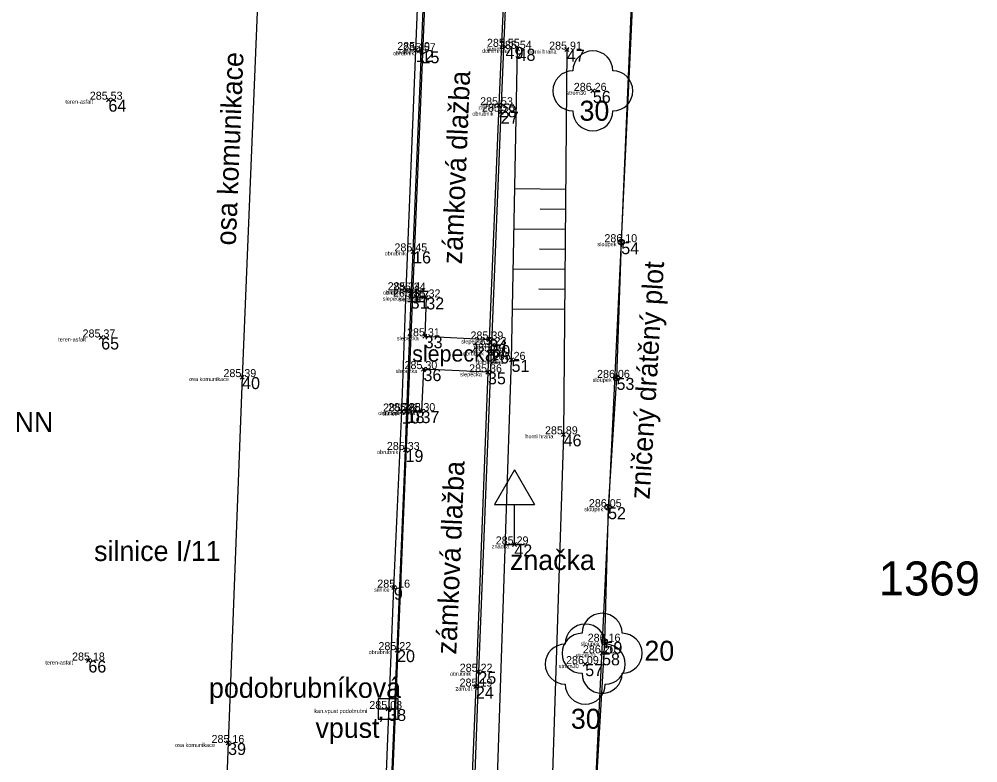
# Model space of a CAD drawing. Extents: x -456675 to -456278, y -1112395 to -1112217.
# Drawn here: x -456327.72 to -456303.78, y -1112312.43 to -1112293.85 of the extents above; entities that cross this region are included whole.
import ezdxf

# ---------------------------------------------------------------- set-up
doc = ezdxf.new("R2010")
doc.units = 0
for name, color, linetype in [('Cislo_bodu', 7, 'Continuous'), ('g_chodniky', 7, 'Continuous'), ('g_dopravni_znaceni', 7, 'Continuous'), ('g_elektrina', 7, 'Continuous'), ('g_kanalizace', 7, 'Continuous'), ('g_komunikace', 7, 'Continuous'), ('g_obrubnik', 7, 'Continuous'), ('g_ploty', 7, 'Continuous'), ('g_terenni_hrany', 7, 'Continuous'), ('g_vegetace', 7, 'Continuous'), ('Katastralni_mapa', 7, 'Continuous'), ('Kod_bodu', 7, 'Continuous'), ('Vyska_bodu', 7, 'Continuous'), ('Znacka_bodu', 7, 'Continuous')]:
    doc.layers.add(name, color=color, linetype=linetype)

msp = doc.modelspace()

# ---------------------------------------------------------------- linework, layer by layer
at = {"layer": 'g_chodniky'}
for points in [[(-456315.433, -1112288.93), (-456315.743, -1112296), (-456315.983, -1112301.85)], [(-456317.929, -1112300.781), (-456317.553, -1112300.8), (-456317.593, -1112301.77), (-456315.983, -1112301.85), (-456316.013, -1112302.67), (-456317.623, -1112302.59), (-456317.673, -1112303.64), (-456318.043, -1112303.64)], [(-456316.013, -1112302.67), (-456316.313, -1112310.52), (-456316.573, -1112316.68)]]:
    msp.add_lwpolyline(points, dxfattribs=at)
at = {"layer": 'g_dopravni_znaceni'}
for p, q in [((-456315.353, -1112305.104), (-456315.853, -1112305.97)), ((-456315.353, -1112305.104), (-456314.853, -1112305.97)), ((-456315.853, -1112305.97), (-456314.853, -1112305.97)), ((-456315.353, -1112306.97), (-456315.353, -1112305.97)), ((-456315.603, -1112306.97), (-456315.103, -1112306.97))]:
    msp.add_line(p, q, dxfattribs=at)
at = {"layer": 'g_kanalizace'}
msp.add_line((-456318.753, -1112311.08), (-456318.253, -1112311.08), dxfattribs=at)
msp.add_lwpolyline([(-456318.753, -1112311.331), (-456318.253, -1112311.331), (-456318.253, -1112310.829), (-456318.753, -1112310.829)], close=True, dxfattribs=at)
at = {"layer": 'g_komunikace'}
for points in [[(-456321.503, -1112286.87), (-456321.723, -1112292.24), (-456322.153, -1112302.79), (-456322.503, -1112311.93), (-456322.863, -1112321.1)], [(-456318.693, -1112316.43), (-456318.363, -1112308.05), (-456318.163, -1112303.65), (-456318.053, -1112300.62), (-456317.813, -1112294.62), (-456317.613, -1112289.62)]]:
    msp.add_lwpolyline(points, dxfattribs=at)
at = {"layer": 'g_obrubnik'}
for points in [[(-456315.393, -1112289.05), (-456315.693, -1112296.16), (-456315.933, -1112302.15), (-456316.253, -1112310.15), (-456316.483, -1112316.6)], [(-456318.573, -1112316.59), (-456318.283, -1112309.61), (-456318.073, -1112304.61), (-456318.043, -1112303.64), (-456317.923, -1112300.63), (-456317.883, -1112299.65), (-456317.673, -1112294.65), (-456317.473, -1112289.63)]]:
    msp.add_lwpolyline(points, dxfattribs=at)
at = {"layer": 'g_ploty'}
msp.add_lwpolyline([(-456312.263, -1112289.35), (-456312.683, -1112299.42), (-456312.803, -1112302.81), (-456313.013, -1112306.04), (-456313.103, -1112309.4), (-456313.303, -1112312.82)], dxfattribs=at)
for centre in [(-456312.683, -1112299.42), (-456312.803, -1112302.81), (-456313.013, -1112306.04), (-456313.103, -1112309.4)]:
    msp.add_circle(centre, 0.075, dxfattribs=at)
at = {"layer": 'g_terenni_hrany'}
for p, q in [((-456315.341, -1112298.083), (-456314.072, -1112298.094)), ((-456314.713, -1112298.589), (-456314.077, -1112298.594)), ((-456315.36, -1112299.083), (-456314.081, -1112299.094)), ((-456314.727, -1112299.589), (-456314.085, -1112299.594)), ((-456315.379, -1112300.083), (-456314.089, -1112300.094)), ((-456314.741, -1112300.589), (-456314.093, -1112300.594)), ((-456315.399, -1112301.083), (-456314.097, -1112301.094))]:
    msp.add_line(p, q, dxfattribs=at)
for points in [[(-456315.783, -1112313.04), (-456315.423, -1112302.36), (-456315.273, -1112294.59)], [(-456314.043, -1112294.61), (-456314.123, -1112304.22), (-456314.423, -1112313.45)]]:
    msp.add_lwpolyline(points, dxfattribs=at)
at = {"layer": 'g_vegetace'}
for centre in [(-456313.393, -1112295.64), (-456313.163, -1112309.69), (-456313.583, -1112309.96)]:
    msp.add_circle(centre, 0.0005, dxfattribs=at)
for centre, start, end in [((-456313.393, -1112295.14), 0, 180), ((-456313.893, -1112295.64), 90, 270), ((-456312.893, -1112295.64), 270, 90), ((-456313.393, -1112296.14), 180, 360), ((-456313.163, -1112309.19), 0, 180), ((-456313.583, -1112309.46), 0, 180), ((-456313.663, -1112309.69), 90, 270), ((-456312.663, -1112309.69), 270, 90), ((-456314.083, -1112309.96), 90, 270), ((-456313.083, -1112309.96), 270, 90), ((-456313.163, -1112310.19), 180, 360), ((-456313.583, -1112310.46), 180, 360)]:
    msp.add_arc(centre, 0.5, start, end, dxfattribs=at)
at = {"layer": 'Katastralni_mapa'}
for points in [[(-456315.703, -1112247.69), (-456320.023, -1112351.98)], [(-456314.273, -1112333.16), (-456312.203, -1112289.34)]]:
    msp.add_lwpolyline(points, dxfattribs=at)
at = {"layer": 'Znacka_bodu'}
for p, q in [((-456315.573, -1112294.54), (-456315.623, -1112294.49)), ((-456315.573, -1112294.54), (-456315.523, -1112294.49)), ((-456317.813, -1112294.62), (-456317.863, -1112294.57)), ((-456317.813, -1112294.62), (-456317.863, -1112294.67)), ((-456317.813, -1112294.62), (-456317.763, -1112294.57)), ((-456317.813, -1112294.62), (-456317.763, -1112294.67)), ((-456317.673, -1112294.65), (-456317.723, -1112294.6)), ((-456317.673, -1112294.65), (-456317.723, -1112294.7)), ((-456317.673, -1112294.65), (-456317.623, -1112294.6)), ((-456317.673, -1112294.65), (-456317.623, -1112294.7)), ((-456315.573, -1112294.54), (-456315.623, -1112294.59)), ((-456315.573, -1112294.54), (-456315.523, -1112294.59)), ((-456315.273, -1112294.59), (-456315.323, -1112294.54)), ((-456315.273, -1112294.59), (-456315.323, -1112294.64)), ((-456315.273, -1112294.59), (-456315.223, -1112294.54)), ((-456315.273, -1112294.59), (-456315.223, -1112294.64)), ((-456314.043, -1112294.61), (-456314.093, -1112294.56)), ((-456314.043, -1112294.61), (-456314.093, -1112294.66)), ((-456314.043, -1112294.61), (-456313.993, -1112294.56)), ((-456314.043, -1112294.61), (-456313.993, -1112294.66)), ((-456313.393, -1112295.64), (-456313.443, -1112295.59)), ((-456313.393, -1112295.64), (-456313.443, -1112295.69)), ((-456313.393, -1112295.64), (-456313.343, -1112295.59)), ((-456313.393, -1112295.64), (-456313.343, -1112295.69)), ((-456325.493, -1112295.86), (-456325.543, -1112295.81)), ((-456325.493, -1112295.86), (-456325.543, -1112295.91)), ((-456325.493, -1112295.86), (-456325.443, -1112295.81)), ((-456325.493, -1112295.86), (-456325.443, -1112295.91)), ((-456315.743, -1112296), (-456315.793, -1112295.95)), ((-456315.743, -1112296), (-456315.693, -1112295.95)), ((-456315.743, -1112296), (-456315.793, -1112296.05)), ((-456315.743, -1112296), (-456315.693, -1112296.05)), ((-456315.693, -1112296.16), (-456315.743, -1112296.11)), ((-456315.693, -1112296.16), (-456315.743, -1112296.21)), ((-456315.693, -1112296.16), (-456315.643, -1112296.11)), ((-456315.693, -1112296.16), (-456315.643, -1112296.21)), ((-456312.683, -1112299.42), (-456312.733, -1112299.37)), ((-456312.683, -1112299.42), (-456312.733, -1112299.47)), ((-456312.683, -1112299.42), (-456312.633, -1112299.37)), ((-456312.683, -1112299.42), (-456312.633, -1112299.47)), ((-456317.883, -1112299.65), (-456317.933, -1112299.6)), ((-456317.883, -1112299.65), (-456317.933, -1112299.7)), ((-456317.883, -1112299.65), (-456317.833, -1112299.6)), ((-456317.883, -1112299.65), (-456317.833, -1112299.7)), ((-456318.053, -1112300.62), (-456318.103, -1112300.57)), ((-456318.053, -1112300.62), (-456318.103, -1112300.67)), ((-456318.053, -1112300.62), (-456318.003, -1112300.57)), ((-456318.053, -1112300.62), (-456318.003, -1112300.67)), ((-456317.943, -1112300.78), (-456317.993, -1112300.73)), ((-456317.923, -1112300.63), (-456317.973, -1112300.58)), ((-456317.923, -1112300.63), (-456317.973, -1112300.68)), ((-456317.943, -1112300.78), (-456317.893, -1112300.73)), ((-456317.923, -1112300.63), (-456317.873, -1112300.58)), ((-456317.923, -1112300.63), (-456317.873, -1112300.68)), ((-456317.943, -1112300.78), (-456317.993, -1112300.83)), ((-456317.943, -1112300.78), (-456317.893, -1112300.83)), ((-456317.553, -1112300.8), (-456317.603, -1112300.75)), ((-456317.553, -1112300.8), (-456317.603, -1112300.85)), ((-456317.553, -1112300.8), (-456317.503, -1112300.75)), ((-456317.553, -1112300.8), (-456317.503, -1112300.85)), ((-456325.673, -1112301.8), (-456325.723, -1112301.75)), ((-456325.673, -1112301.8), (-456325.723, -1112301.85)), ((-456325.673, -1112301.8), (-456325.623, -1112301.75)), ((-456325.673, -1112301.8), (-456325.623, -1112301.85)), ((-456317.593, -1112301.77), (-456317.643, -1112301.72)), ((-456317.593, -1112301.77), (-456317.643, -1112301.82)), ((-456317.593, -1112301.77), (-456317.543, -1112301.72)), ((-456317.593, -1112301.77), (-456317.543, -1112301.82)), ((-456315.983, -1112301.85), (-456316.033, -1112301.8)), ((-456315.983, -1112301.85), (-456316.033, -1112301.9)), ((-456315.983, -1112301.85), (-456315.933, -1112301.8)), ((-456315.983, -1112301.85), (-456315.933, -1112301.9)), ((-456315.903, -1112301.99), (-456315.953, -1112301.94)), ((-456315.903, -1112301.99), (-456315.853, -1112301.94)), ((-456315.933, -1112302.15), (-456315.983, -1112302.1)), ((-456315.933, -1112302.15), (-456315.983, -1112302.2)), ((-456315.903, -1112301.99), (-456315.953, -1112302.04)), ((-456315.933, -1112302.15), (-456315.883, -1112302.1)), ((-456315.933, -1112302.15), (-456315.883, -1112302.2)), ((-456315.903, -1112301.99), (-456315.853, -1112302.04)), ((-456315.423, -1112302.36), (-456315.473, -1112302.31)), ((-456315.423, -1112302.36), (-456315.473, -1112302.41)), ((-456315.423, -1112302.36), (-456315.373, -1112302.31)), ((-456315.423, -1112302.36), (-456315.373, -1112302.41)), ((-456317.623, -1112302.59), (-456317.673, -1112302.54)), ((-456317.623, -1112302.59), (-456317.673, -1112302.64)), ((-456317.623, -1112302.59), (-456317.573, -1112302.54)), ((-456317.623, -1112302.59), (-456317.573, -1112302.64)), ((-456316.013, -1112302.67), (-456316.063, -1112302.62)), ((-456316.013, -1112302.67), (-456315.963, -1112302.62)), ((-456322.153, -1112302.79), (-456322.203, -1112302.74)), ((-456322.153, -1112302.79), (-456322.203, -1112302.84)), ((-456322.153, -1112302.79), (-456322.103, -1112302.74)), ((-456322.153, -1112302.79), (-456322.103, -1112302.84)), ((-456316.013, -1112302.67), (-456316.063, -1112302.72)), ((-456316.013, -1112302.67), (-456315.963, -1112302.72)), ((-456312.803, -1112302.81), (-456312.853, -1112302.76)), ((-456312.803, -1112302.81), (-456312.853, -1112302.86)), ((-456312.803, -1112302.81), (-456312.753, -1112302.76)), ((-456312.803, -1112302.81), (-456312.753, -1112302.86)), ((-456318.163, -1112303.65), (-456318.213, -1112303.6)), ((-456318.163, -1112303.65), (-456318.113, -1112303.6)), ((-456318.043, -1112303.64), (-456318.093, -1112303.59)), ((-456318.043, -1112303.64), (-456317.993, -1112303.59)), ((-456317.673, -1112303.64), (-456317.723, -1112303.59)), ((-456317.673, -1112303.64), (-456317.623, -1112303.59)), ((-456318.163, -1112303.65), (-456318.213, -1112303.7)), ((-456318.163, -1112303.65), (-456318.113, -1112303.7)), ((-456318.043, -1112303.64), (-456318.093, -1112303.69)), ((-456318.043, -1112303.64), (-456317.993, -1112303.69)), ((-456317.673, -1112303.64), (-456317.723, -1112303.69)), ((-456317.673, -1112303.64), (-456317.623, -1112303.69)), ((-456314.123, -1112304.22), (-456314.173, -1112304.17)), ((-456314.123, -1112304.22), (-456314.173, -1112304.27)), ((-456314.123, -1112304.22), (-456314.073, -1112304.17)), ((-456314.123, -1112304.22), (-456314.073, -1112304.27)), ((-456318.073, -1112304.61), (-456318.123, -1112304.56)), ((-456318.073, -1112304.61), (-456318.023, -1112304.56)), ((-456318.073, -1112304.61), (-456318.123, -1112304.66)), ((-456318.073, -1112304.61), (-456318.023, -1112304.66)), ((-456313.013, -1112306.04), (-456313.063, -1112305.99)), ((-456313.013, -1112306.04), (-456312.963, -1112305.99)), ((-456313.013, -1112306.04), (-456313.063, -1112306.09)), ((-456313.013, -1112306.04), (-456312.963, -1112306.09)), ((-456315.353, -1112306.97), (-456315.403, -1112306.92)), ((-456315.353, -1112306.97), (-456315.403, -1112307.02)), ((-456315.353, -1112306.97), (-456315.303, -1112306.92)), ((-456315.353, -1112306.97), (-456315.303, -1112307.02)), ((-456318.363, -1112308.05), (-456318.413, -1112308)), ((-456318.363, -1112308.05), (-456318.413, -1112308.1)), ((-456318.363, -1112308.05), (-456318.313, -1112308)), ((-456318.363, -1112308.05), (-456318.313, -1112308.1)), ((-456313.103, -1112309.4), (-456313.153, -1112309.35)), ((-456313.103, -1112309.4), (-456313.053, -1112309.35)), ((-456318.283, -1112309.61), (-456318.333, -1112309.56)), ((-456318.283, -1112309.61), (-456318.233, -1112309.56)), ((-456313.103, -1112309.4), (-456313.153, -1112309.45)), ((-456313.103, -1112309.4), (-456313.053, -1112309.45)), ((-456325.993, -1112309.87), (-456326.043, -1112309.82)), ((-456325.993, -1112309.87), (-456325.943, -1112309.82)), ((-456318.283, -1112309.61), (-456318.333, -1112309.66)), ((-456318.283, -1112309.61), (-456318.233, -1112309.66)), ((-456313.163, -1112309.69), (-456313.213, -1112309.64)), ((-456313.163, -1112309.69), (-456313.213, -1112309.74)), ((-456313.163, -1112309.69), (-456313.113, -1112309.64)), ((-456313.163, -1112309.69), (-456313.113, -1112309.74)), ((-456325.993, -1112309.87), (-456326.043, -1112309.92)), ((-456325.993, -1112309.87), (-456325.943, -1112309.92)), ((-456313.583, -1112309.96), (-456313.633, -1112309.91)), ((-456313.583, -1112309.96), (-456313.633, -1112310.01)), ((-456313.583, -1112309.96), (-456313.533, -1112309.91)), ((-456313.583, -1112309.96), (-456313.533, -1112310.01)), ((-456316.253, -1112310.15), (-456316.303, -1112310.1)), ((-456316.253, -1112310.15), (-456316.303, -1112310.2)), ((-456316.253, -1112310.15), (-456316.203, -1112310.1)), ((-456316.253, -1112310.15), (-456316.203, -1112310.2)), ((-456316.313, -1112310.52), (-456316.363, -1112310.47)), ((-456316.313, -1112310.52), (-456316.363, -1112310.57)), ((-456316.313, -1112310.52), (-456316.263, -1112310.47)), ((-456316.313, -1112310.52), (-456316.263, -1112310.57)), ((-456318.503, -1112311.08), (-456318.553, -1112311.03)), ((-456318.503, -1112311.08), (-456318.453, -1112311.03)), ((-456318.503, -1112311.08), (-456318.553, -1112311.13)), ((-456318.503, -1112311.08), (-456318.453, -1112311.13)), ((-456322.503, -1112311.93), (-456322.553, -1112311.88)), ((-456322.503, -1112311.93), (-456322.553, -1112311.98)), ((-456322.503, -1112311.93), (-456322.453, -1112311.88)), ((-456322.503, -1112311.93), (-456322.453, -1112311.98))]:
    msp.add_line(p, q, dxfattribs=at)

# ---------------------------------------------------------------- texts
at = {"layer": 'Cislo_bodu'}
for s, p in [('12', (-456317.813, -1112294.92)), ('15', (-456317.673, -1112294.95)), ('49', (-456315.573, -1112294.84)), ('48', (-456315.273, -1112294.89)), ('47', (-456314.043, -1112294.91)), ('56', (-456313.393, -1112295.94)), ('64', (-456325.493, -1112296.16)), ('28', (-456315.743, -1112296.3)), ('27', (-456315.693, -1112296.46)), ('54', (-456312.683, -1112299.72)), ('16', (-456317.883, -1112299.95)), ('11', (-456318.053, -1112300.92)), ('17', (-456317.923, -1112300.93)), ('31', (-456317.943, -1112301.08)), ('32', (-456317.553, -1112301.1)), ('65', (-456325.673, -1112302.1)), ('33', (-456317.593, -1112302.07)), ('34', (-456315.983, -1112302.15)), ('26', (-456315.933, -1112302.45)), ('50', (-456315.903, -1112302.29)), ('51', (-456315.423, -1112302.66)), ('36', (-456317.623, -1112302.89)), ('40', (-456322.153, -1112303.09)), ('35', (-456316.013, -1112302.97)), ('53', (-456312.803, -1112303.11)), ('10', (-456318.163, -1112303.95)), ('18', (-456318.043, -1112303.94)), ('37', (-456317.673, -1112303.94)), ('46', (-456314.123, -1112304.52)), ('19', (-456318.073, -1112304.91)), ('52', (-456313.013, -1112306.34)), ('42', (-456315.353, -1112307.27)), ('9', (-456318.363, -1112308.35)), ('20', (-456318.283, -1112309.91)), ('59', (-456313.103, -1112309.7)), ('58', (-456313.163, -1112309.99)), ('66', (-456325.993, -1112310.17)), ('57', (-456313.583, -1112310.26)), ('25', (-456316.253, -1112310.45)), ('24', (-456316.313, -1112310.82)), ('38', (-456318.503, -1112311.38)), ('39', (-456322.503, -1112312.23))]:
    msp.add_text(s, height=0.3, dxfattribs=at).set_placement(p)
at = {"layer": 'g_chodniky'}
for rotation, p in [(87.5314, (-456316.663, -1112299.978)), (87.5119, (-456316.806, -1112309.724))]:
    msp.add_text('zámková dlažba', height=0.5, rotation=rotation, dxfattribs=at).set_placement(p)
msp.add_text('slepecká', height=0.4, dxfattribs=at).set_placement((-456317.905, -1112302.403))
at = {"layer": 'g_dopravni_znaceni'}
msp.add_text('značka', height=0.5, dxfattribs=at).set_placement((-456315.462, -1112307.608))
at = {"layer": 'g_elektrina'}
msp.add_text('dvojitý sloup NN', height=0.5, dxfattribs=at).set_placement((-456331.699, -1112304.158))
at = {"layer": 'g_kanalizace'}
for s, p in [('podobrubníková', (-456322.98, -1112310.802)), ('vpusť', (-456320.32, -1112311.802))]:
    msp.add_text(s, height=0.5, dxfattribs=at).set_placement(p)
at = {"layer": 'g_komunikace'}
msp.add_text('osa komunikace', height=0.5, rotation=87.675, dxfattribs=at).set_placement((-456322.313, -1112299.508))
msp.add_text('silnice I/11', height=0.5, dxfattribs=at).set_placement((-456325.85, -1112307.384))
at = {"layer": 'g_ploty'}
msp.add_text('zničený drátěný plot', height=0.5, rotation=86.4834, dxfattribs=at).set_placement((-456311.978, -1112305.852))
at = {"layer": 'g_vegetace'}
for s, p in [('30', (-456313.726, -1112296.386)), ('20', (-456312.105, -1112309.876)), ('30', (-456313.942, -1112311.575))]:
    msp.add_text(s, height=0.5, dxfattribs=at).set_placement(p)
at = {"layer": 'Katastralni_mapa'}
msp.add_text('1369', height=0.85, dxfattribs=at).set_placement((-456306.253, -1112308.245))
at = {"layer": 'Kod_bodu'}
for s, p in [('obrubnik', (-456318.384, -1112294.75)), ('silnice', (-456318.304, -1112294.72)), ('dolni hrana', (-456316.164, -1112294.69)), ('teren', (-456316.039, -1112294.64)), ('horni hrana', (-456314.999, -1112294.71)), ('strom30', (-456314.056, -1112295.74)), ('teren-asfalt', (-456326.567, -1112295.96)), ('obrubnik', (-456316.404, -1112296.26)), ('zam.dl.', (-456316.255, -1112296.1)), ('sloupek', (-456313.279, -1112299.52)), ('obrubnik', (-456318.594, -1112299.75)), ('obrubnik', (-456318.634, -1112300.73)), ('silnice', (-456318.544, -1112300.72)), ('slepecka', (-456318.639, -1112300.88)), ('slepecka', (-456318.249, -1112300.9)), ('teren-asfalt', (-456326.747, -1112301.9)), ('slepecka', (-456318.289, -1112301.87)), ('slepecka', (-456316.679, -1112301.95)), ('obrubnik', (-456316.644, -1112302.25)), ('teren', (-456316.369, -1112302.09)), ('dolni hrana', (-456316.314, -1112302.46)), ('slepecka', (-456318.319, -1112302.69)), ('osa komunikace', (-456323.478, -1112302.89)), ('slepecka', (-456316.709, -1112302.77)), ('sloupek', (-456313.399, -1112302.91)), ('obrubnik', (-456318.754, -1112303.74)), ('silnice', (-456318.654, -1112303.75)), ('slepecka', (-456318.369, -1112303.74)), ('horni hrana', (-456315.079, -1112304.32)), ('obrubnik', (-456318.784, -1112304.71)), ('sloupek', (-456313.609, -1112306.14)), ('znacka', (-456315.92, -1112307.07)), ('silnice', (-456318.854, -1112308.15)), ('obrubnik', (-456318.994, -1112309.71)), ('sloupek', (-456313.699, -1112309.5)), ('strom20', (-456313.826, -1112309.79)), ('teren-asfalt', (-456327.067, -1112309.97)), ('strom30', (-456314.246, -1112310.06)), ('obrubnik', (-456316.964, -1112310.25)), ('zam.dl.', (-456316.825, -1112310.62)), ('kan.vpust podobrubni', (-456320.349, -1112311.18)), ('osa komunikace', (-456323.828, -1112312.03))]:
    msp.add_text(s, height=0.1, dxfattribs=at).set_placement(p)
at = {"layer": 'Vyska_bodu'}
for s, p in [('285.49', (-456318.279, -1112294.62)), ('285.57', (-456318.138, -1112294.65)), ('285.55', (-456316.038, -1112294.54)), ('285.54', (-456315.738, -1112294.59)), ('285.91', (-456314.485, -1112294.61)), ('286.26', (-456313.869, -1112295.64)), ('285.53', (-456325.958, -1112295.86)), ('285.53', (-456316.208, -1112296)), ('285.56', (-456316.163, -1112296.16)), ('286.10', (-456313.105, -1112299.42)), ('285.45', (-456318.348, -1112299.65)), ('285.34', (-456318.518, -1112300.62)), ('285.34', (-456318.388, -1112300.63)), ('285.31', (-456318.384, -1112300.78)), ('285.32', (-456318.018, -1112300.8)), ('285.37', (-456326.138, -1112301.8)), ('285.31', (-456318.034, -1112301.77)), ('285.39', (-456316.449, -1112301.85)), ('285.23', (-456316.368, -1112301.99)), ('285.40', (-456316.407, -1112302.15)), ('285.26', (-456315.893, -1112302.36)), ('285.30', (-456318.097, -1112302.59)), ('285.39', (-456322.619, -1112302.79)), ('285.36', (-456316.483, -1112302.67)), ('286.06', (-456313.288, -1112302.81)), ('285.26', (-456318.633, -1112303.65)), ('285.28', (-456318.508, -1112303.64)), ('285.30', (-456318.147, -1112303.64)), ('285.89', (-456314.589, -1112304.22)), ('285.33', (-456318.538, -1112304.61)), ('286.05', (-456313.492, -1112306.04)), ('285.29', (-456315.819, -1112306.97)), ('285.16', (-456318.777, -1112308.05)), ('286.16', (-456313.522, -1112309.4)), ('285.22', (-456318.748, -1112309.61)), ('286.20', (-456313.642, -1112309.69)), ('285.18', (-456326.401, -1112309.87)), ('286.09', (-456314.063, -1112309.96)), ('285.22', (-456316.718, -1112310.15)), ('285.19', (-456316.722, -1112310.52)), ('285.08', (-456318.977, -1112311.08)), ('285.16', (-456322.917, -1112311.93))]:
    msp.add_text(s, height=0.2, dxfattribs=at).set_placement(p)

doc.saveas('drawing.dxf')
